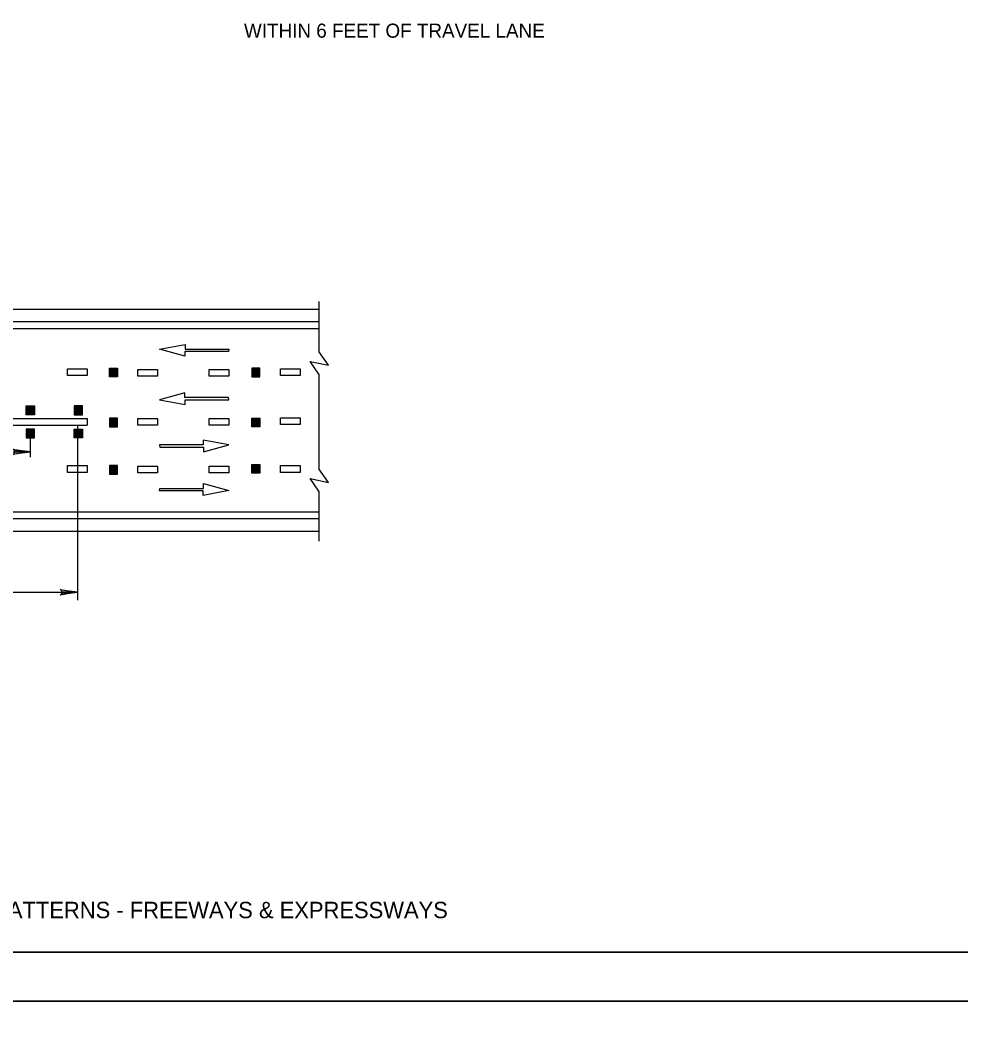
# Model space of a CAD drawing. Extents: x 639362 to 641108, y 298458 to 299646.
# Drawn here: x 639652.3 to 639939.1, y 299044.4 to 299350.7 of the extents above; entities that cross this region are included whole.
import ezdxf

# ---------------------------------------------------------------- set-up
doc = ezdxf.new("R2010")
doc.units = 0
for name, color, linetype in [('1', 7, 'Continuous'), ('2', 7, 'Continuous'), ('PLT-BNDY', 7, 'Continuous')]:
    doc.layers.add(name, color=color, linetype=linetype)

msp = doc.modelspace()

# ---------------------------------------------------------------- linework, layer by layer
at = {"layer": '1'}
for p, q in [((640188.31, 299066.63), (639402.31, 299066.63)), ((639402.31, 299066.63), (639988.31, 299066.63))]:
    msp.add_line(p, q, dxfattribs=at)
at = {"layer": '2'}
for p, q in [((639743.31, 299264.95), (639743.31, 299249.67)), ((639583.1, 299262.59), (639743.31, 299262.59)), ((639583.09, 299258.81), (639743.31, 299258.81)), ((639583.09, 299256.74), (639743.31, 299256.74)), ((639694.78, 299250.39), (639702.59, 299251.86)), ((639702.59, 299251.86), (639702.59, 299250.42)), ((639702.51, 299248.27), (639694.78, 299250.39)), ((639715.83, 299249.72), (639702.51, 299249.72)), ((639702.51, 299249.72), (639702.51, 299248.27)), ((639702.59, 299250.42), (639715.91, 299250.42)), ((639715.91, 299250.39), (639715.83, 299249.72)), ((639715.91, 299250.42), (639715.91, 299250.39)), ((639746.26, 299245.54), (639743.31, 299249.67)), ((639743.31, 299242.8), (639740.73, 299246.67)), ((639740.73, 299246.67), (639746.26, 299245.54)), ((639666.72, 299242.34), (639666.72, 299244.4)), ((639666.72, 299244.4), (639672.74, 299244.4)), ((639672.74, 299244.4), (639672.74, 299242.34)), ((639679.48, 299244.59), (639681.97, 299244.59)), ((639679.48, 299241.93), (639679.48, 299244.59)), ((639679.66, 299244.45), (639681.79, 299244.45)), ((639679.66, 299242.06), (639679.66, 299244.45)), ((639679.84, 299244.28), (639681.62, 299244.28)), ((639679.84, 299242.24), (639679.84, 299244.28)), ((639680.02, 299244.1), (639681.44, 299244.1)), ((639680.02, 299242.41), (639680.02, 299244.1)), ((639680.19, 299243.92), (639681.26, 299243.92)), ((639680.19, 299242.59), (639680.19, 299243.92)), ((639681.26, 299242.59), (639680.19, 299242.59)), ((639680.37, 299242.77), (639680.37, 299243.74)), ((639680.37, 299243.74), (639681.08, 299243.74)), ((639681.08, 299242.77), (639680.37, 299242.77)), ((639680.55, 299243.57), (639680.91, 299243.57)), ((639680.55, 299242.95), (639680.55, 299243.57)), ((639680.91, 299242.95), (639680.55, 299242.95)), ((639680.73, 299243.39), (639680.73, 299243.12)), ((639680.91, 299243.57), (639680.91, 299242.95)), ((639681.08, 299243.74), (639681.08, 299242.77)), ((639681.26, 299243.92), (639681.26, 299242.59)), ((639681.44, 299244.1), (639681.44, 299242.41)), ((639681.62, 299244.28), (639681.62, 299242.24)), ((639681.79, 299244.45), (639681.79, 299242.06)), ((639681.97, 299244.59), (639681.97, 299241.93)), ((639688.17, 299242.15), (639688.17, 299244.22)), ((639688.17, 299244.22), (639694.19, 299244.22)), ((639694.19, 299244.22), (639694.19, 299242.15)), ((639709.87, 299242.15), (639709.87, 299244.22)), ((639709.87, 299244.22), (639715.89, 299244.22)), ((639715.89, 299244.22), (639715.89, 299242.15)), ((639725.39, 299244.59), (639722.89, 299244.59)), ((639722.89, 299244.59), (639722.89, 299241.93)), ((639725.2, 299244.45), (639723.07, 299244.45)), ((639723.07, 299244.45), (639723.07, 299242.06)), ((639725.02, 299244.28), (639723.25, 299244.28)), ((639723.25, 299244.28), (639723.25, 299242.24)), ((639724.84, 299244.1), (639723.43, 299244.1)), ((639723.43, 299244.1), (639723.43, 299242.41)), ((639724.67, 299243.92), (639723.6, 299243.92)), ((639723.6, 299243.92), (639723.6, 299242.59)), ((639723.6, 299242.59), (639724.67, 299242.59)), ((639723.78, 299243.74), (639723.78, 299242.77)), ((639724.49, 299243.74), (639723.78, 299243.74)), ((639723.78, 299242.77), (639724.49, 299242.77)), ((639724.31, 299243.57), (639723.96, 299243.57)), ((639723.96, 299243.57), (639723.96, 299242.95)), ((639723.96, 299242.95), (639724.31, 299242.95)), ((639724.14, 299243.39), (639724.14, 299243.12)), ((639724.31, 299242.95), (639724.31, 299243.57)), ((639724.49, 299242.77), (639724.49, 299243.74)), ((639724.67, 299242.59), (639724.67, 299243.92)), ((639724.84, 299242.41), (639724.84, 299244.1)), ((639725.02, 299242.24), (639725.02, 299244.28)), ((639725.2, 299242.06), (639725.2, 299244.45)), ((639725.39, 299241.93), (639725.39, 299244.59)), ((639731.64, 299242.34), (639731.64, 299244.4)), ((639731.64, 299244.4), (639737.65, 299244.4)), ((639737.65, 299244.4), (639737.65, 299242.34)), ((639743.31, 299242.8), (639743.31, 299213.94)), ((639672.74, 299242.34), (639666.72, 299242.34)), ((639681.97, 299241.93), (639679.48, 299241.93)), ((639681.79, 299242.06), (639679.66, 299242.06)), ((639681.62, 299242.24), (639679.84, 299242.24)), ((639681.44, 299242.41), (639680.02, 299242.41)), ((639694.19, 299242.15), (639688.17, 299242.15)), ((639715.89, 299242.15), (639709.87, 299242.15)), ((639722.89, 299241.93), (639725.39, 299241.93)), ((639723.07, 299242.06), (639725.2, 299242.06)), ((639723.25, 299242.24), (639725.02, 299242.24)), ((639723.43, 299242.41), (639724.84, 299242.41)), ((639737.65, 299242.34), (639731.64, 299242.34)), ((639702.51, 299237.11), (639694.78, 299234.99)), ((639702.51, 299235.66), (639702.51, 299237.11)), ((639694.78, 299234.99), (639702.59, 299233.51)), ((639715.83, 299235.66), (639702.51, 299235.66)), ((639702.59, 299233.51), (639702.59, 299234.96)), ((639702.59, 299234.96), (639715.91, 299234.96)), ((639715.91, 299234.99), (639715.83, 299235.66)), ((639715.91, 299234.96), (639715.91, 299234.99)), ((639654.13, 299230.43), (639654.13, 299233.09)), ((639654.13, 299233.09), (639656.63, 299233.09)), ((639656.63, 299230.43), (639654.13, 299230.43)), ((639654.31, 299230.57), (639654.31, 299232.96)), ((639654.31, 299232.96), (639656.44, 299232.96)), ((639656.44, 299230.57), (639654.31, 299230.57)), ((639654.49, 299230.74), (639654.49, 299232.78)), ((639654.49, 299232.78), (639656.26, 299232.78)), ((639656.26, 299230.74), (639654.49, 299230.74)), ((639654.67, 299230.92), (639654.67, 299232.61)), ((639654.67, 299232.61), (639656.09, 299232.61)), ((639656.09, 299230.92), (639654.67, 299230.92)), ((639654.85, 299231.1), (639654.85, 299232.43)), ((639654.85, 299232.43), (639655.91, 299232.43)), ((639655.91, 299231.1), (639654.85, 299231.1)), ((639655.02, 299231.28), (639655.02, 299232.25)), ((639655.02, 299232.25), (639655.73, 299232.25)), ((639655.73, 299231.28), (639655.02, 299231.28)), ((639655.2, 299231.45), (639655.2, 299232.07)), ((639655.2, 299232.07), (639655.55, 299232.07)), ((639655.55, 299231.45), (639655.2, 299231.45)), ((639655.38, 299231.63), (639655.38, 299231.9)), ((639655.55, 299232.07), (639655.55, 299231.45)), ((639655.73, 299232.25), (639655.73, 299231.28)), ((639655.91, 299232.43), (639655.91, 299231.1)), ((639656.09, 299232.61), (639656.09, 299230.92)), ((639656.26, 299232.78), (639656.26, 299230.74)), ((639656.44, 299232.96), (639656.44, 299230.57)), ((639656.63, 299233.09), (639656.63, 299230.43)), ((639671.26, 299233.09), (639668.77, 299233.09)), ((639668.77, 299233.09), (639668.77, 299230.43)), ((639668.77, 299230.43), (639671.26, 299230.43)), ((639671.08, 299232.96), (639668.95, 299232.96)), ((639668.95, 299232.96), (639668.95, 299230.57)), ((639668.95, 299230.57), (639671.08, 299230.57)), ((639670.9, 299232.78), (639669.13, 299232.78)), ((639669.13, 299232.78), (639669.13, 299230.74)), ((639669.13, 299230.74), (639670.9, 299230.74)), ((639670.73, 299232.61), (639669.31, 299232.61)), ((639669.31, 299232.61), (639669.31, 299230.92)), ((639669.31, 299230.92), (639670.73, 299230.92)), ((639670.55, 299232.43), (639669.48, 299232.43)), ((639669.48, 299232.43), (639669.48, 299231.1)), ((639669.48, 299231.1), (639670.55, 299231.1)), ((639670.37, 299232.25), (639669.66, 299232.25)), ((639669.66, 299232.25), (639669.66, 299231.28)), ((639669.66, 299231.28), (639670.37, 299231.28)), ((639670.2, 299232.07), (639669.84, 299232.07)), ((639669.84, 299232.07), (639669.84, 299231.45)), ((639669.84, 299231.45), (639670.2, 299231.45)), ((639670.02, 299231.63), (639670.02, 299231.9)), ((639670.2, 299231.45), (639670.2, 299232.07)), ((639670.37, 299231.28), (639670.37, 299232.25)), ((639670.55, 299231.1), (639670.55, 299232.43)), ((639670.73, 299230.92), (639670.73, 299232.61)), ((639670.9, 299230.74), (639670.9, 299232.78)), ((639671.08, 299230.57), (639671.08, 299232.96)), ((639671.26, 299230.43), (639671.26, 299233.09)), ((639583.05, 299229.28), (639672.74, 299229.28)), ((639672.74, 299229.28), (639672.74, 299227.21)), ((639681.97, 299229.39), (639679.48, 299229.39)), ((639679.48, 299229.39), (639679.48, 299226.73)), ((639681.79, 299229.26), (639679.66, 299229.26)), ((639679.66, 299229.26), (639679.66, 299226.86)), ((639681.62, 299229.08), (639679.84, 299229.08)), ((639679.84, 299229.08), (639679.84, 299227.04)), ((639681.44, 299228.9), (639680.02, 299228.9)), ((639680.02, 299228.9), (639680.02, 299227.22)), ((639681.26, 299228.73), (639680.19, 299228.73)), ((639680.19, 299228.73), (639680.19, 299227.39)), ((639680.19, 299227.39), (639681.26, 299227.39)), ((639681.08, 299228.55), (639680.37, 299228.55)), ((639680.37, 299228.55), (639680.37, 299227.57)), ((639680.37, 299227.57), (639681.08, 299227.57)), ((639680.91, 299228.37), (639680.55, 299228.37)), ((639680.55, 299228.37), (639680.55, 299227.75)), ((639680.55, 299227.75), (639680.91, 299227.75)), ((639680.73, 299227.93), (639680.73, 299228.19)), ((639680.91, 299227.75), (639680.91, 299228.37)), ((639681.08, 299227.57), (639681.08, 299228.55)), ((639681.26, 299227.39), (639681.26, 299228.73)), ((639681.44, 299227.22), (639681.44, 299228.9)), ((639681.62, 299227.04), (639681.62, 299229.08)), ((639681.79, 299226.86), (639681.79, 299229.26)), ((639681.97, 299226.73), (639681.97, 299229.39)), ((639688.17, 299227.21), (639688.17, 299229.28)), ((639688.17, 299229.28), (639694.19, 299229.28)), ((639694.19, 299229.28), (639694.19, 299227.21)), ((639709.87, 299227.21), (639709.87, 299229.28)), ((639709.87, 299229.28), (639715.89, 299229.28)), ((639715.89, 299229.28), (639715.89, 299227.21)), ((639722.89, 299226.73), (639722.89, 299229.39)), ((639722.89, 299229.39), (639725.39, 299229.39)), ((639723.07, 299226.86), (639723.07, 299229.26)), ((639723.07, 299229.26), (639725.2, 299229.26)), ((639723.25, 299227.04), (639723.25, 299229.08)), ((639723.25, 299229.08), (639725.02, 299229.08)), ((639723.43, 299227.22), (639723.43, 299228.9)), ((639723.43, 299228.9), (639724.84, 299228.9)), ((639723.6, 299227.39), (639723.6, 299228.73)), ((639723.6, 299228.73), (639724.67, 299228.73)), ((639724.67, 299227.39), (639723.6, 299227.39)), ((639723.78, 299227.57), (639723.78, 299228.55)), ((639723.78, 299228.55), (639724.49, 299228.55)), ((639724.49, 299227.57), (639723.78, 299227.57)), ((639723.96, 299227.75), (639723.96, 299228.37)), ((639723.96, 299228.37), (639724.31, 299228.37)), ((639724.31, 299227.75), (639723.96, 299227.75)), ((639724.14, 299227.93), (639724.14, 299228.19)), ((639724.31, 299228.37), (639724.31, 299227.75)), ((639724.49, 299228.55), (639724.49, 299227.57)), ((639724.67, 299228.73), (639724.67, 299227.39)), ((639724.84, 299228.9), (639724.84, 299227.22)), ((639725.02, 299229.08), (639725.02, 299227.04)), ((639725.2, 299229.26), (639725.2, 299226.86)), ((639725.39, 299229.39), (639725.39, 299226.73)), ((639731.64, 299227.4), (639731.64, 299229.46)), ((639731.64, 299229.46), (639737.65, 299229.46)), ((639737.65, 299227.4), (639731.64, 299227.4)), ((639737.65, 299229.46), (639737.65, 299227.4)), ((639583.05, 299227.21), (639672.74, 299227.21)), ((639656.63, 299226.05), (639654.13, 299226.05)), ((639654.13, 299226.05), (639654.13, 299223.4)), ((639656.44, 299225.92), (639654.31, 299225.92)), ((639654.31, 299225.92), (639654.31, 299223.53)), ((639656.26, 299225.75), (639654.49, 299225.75)), ((639654.49, 299225.75), (639654.49, 299223.71)), ((639656.09, 299225.57), (639654.67, 299225.57)), ((639654.67, 299225.57), (639654.67, 299223.88)), ((639655.91, 299225.39), (639654.85, 299225.39)), ((639654.85, 299225.39), (639654.85, 299224.06)), ((639655.02, 299225.21), (639655.02, 299224.24)), ((639655.73, 299225.21), (639655.02, 299225.21)), ((639655.02, 299224.24), (639655.73, 299224.24)), ((639655.55, 299225.03), (639655.2, 299225.03)), ((639655.2, 299225.03), (639655.2, 299224.41)), ((639655.2, 299224.41), (639655.55, 299224.41)), ((639655.38, 299224.86), (639655.38, 299224.59)), ((639655.55, 299224.41), (639655.55, 299225.03)), ((639655.73, 299224.24), (639655.73, 299225.21)), ((639655.91, 299224.06), (639655.91, 299225.39)), ((639656.09, 299223.88), (639656.09, 299225.57)), ((639656.26, 299223.71), (639656.26, 299225.75)), ((639656.44, 299223.53), (639656.44, 299225.92)), ((639656.63, 299223.4), (639656.63, 299226.05)), ((639668.77, 299226.05), (639671.26, 299226.05)), ((639668.77, 299223.4), (639668.77, 299226.05)), ((639668.95, 299225.92), (639671.08, 299225.92)), ((639668.95, 299223.53), (639668.95, 299225.92)), ((639669.13, 299225.75), (639670.9, 299225.75)), ((639669.13, 299223.71), (639669.13, 299225.75)), ((639669.31, 299225.57), (639670.73, 299225.57)), ((639669.31, 299223.88), (639669.31, 299225.57)), ((639669.48, 299225.39), (639670.55, 299225.39)), ((639669.48, 299224.06), (639669.48, 299225.39)), ((639669.66, 299224.24), (639669.66, 299225.21)), ((639669.66, 299225.21), (639670.37, 299225.21)), ((639670.37, 299224.24), (639669.66, 299224.24)), ((639669.77, 299227.21), (639669.77, 299173.91)), ((639669.84, 299225.03), (639670.2, 299225.03)), ((639669.84, 299224.41), (639669.84, 299225.03)), ((639670.2, 299224.41), (639669.84, 299224.41)), ((639670.02, 299224.86), (639670.02, 299224.59)), ((639670.2, 299225.03), (639670.2, 299224.41)), ((639670.37, 299225.21), (639670.37, 299224.24)), ((639670.55, 299225.39), (639670.55, 299224.06)), ((639670.73, 299225.57), (639670.73, 299223.88)), ((639670.9, 299225.75), (639670.9, 299223.71)), ((639671.08, 299225.92), (639671.08, 299223.53)), ((639671.26, 299226.05), (639671.26, 299223.4)), ((639679.48, 299226.73), (639681.97, 299226.73)), ((639679.66, 299226.86), (639681.79, 299226.86)), ((639679.84, 299227.04), (639681.62, 299227.04)), ((639680.02, 299227.22), (639681.44, 299227.22)), ((639694.19, 299227.21), (639688.17, 299227.21)), ((639715.89, 299227.21), (639709.87, 299227.21)), ((639725.39, 299226.73), (639722.89, 299226.73)), ((639725.2, 299226.86), (639723.07, 299226.86)), ((639725.02, 299227.04), (639723.25, 299227.04)), ((639724.84, 299227.22), (639723.43, 299227.22)), ((639654.13, 299223.4), (639656.63, 299223.4)), ((639654.31, 299223.53), (639656.44, 299223.53)), ((639654.49, 299223.71), (639656.26, 299223.71)), ((639654.67, 299223.88), (639656.09, 299223.88)), ((639654.85, 299224.06), (639655.91, 299224.06)), ((639655.34, 299224.09), (639655.34, 299217.48)), ((639671.26, 299223.4), (639668.77, 299223.4)), ((639671.08, 299223.53), (639668.95, 299223.53)), ((639670.9, 299223.71), (639669.13, 299223.71)), ((639670.73, 299223.88), (639669.31, 299223.88)), ((639670.55, 299224.06), (639669.48, 299224.06)), ((639694.76, 299221.26), (639694.76, 299221.23)), ((639708.08, 299221.26), (639694.76, 299221.26)), ((639694.76, 299221.23), (639694.84, 299220.56)), ((639715.89, 299221.23), (639708.08, 299222.71)), ((639708.08, 299222.71), (639708.08, 299221.26)), ((639708.16, 299219.12), (639715.89, 299221.23)), ((639640.26, 299219.12), (639655.34, 299219.12)), ((639694.84, 299220.56), (639708.16, 299220.56)), ((639708.16, 299220.56), (639708.16, 299219.12)), ((639722.89, 299212.56), (639722.89, 299215.22)), ((639722.89, 299215.22), (639725.39, 299215.22)), ((639723.07, 299212.69), (639723.07, 299215.09)), ((639723.07, 299215.09), (639725.2, 299215.09)), ((639725.2, 299215.09), (639725.2, 299212.69)), ((639725.39, 299215.22), (639725.39, 299212.56)), ((639666.72, 299212.85), (639666.72, 299214.91)), ((639666.72, 299214.91), (639672.74, 299214.91)), ((639672.74, 299212.85), (639666.72, 299212.85)), ((639672.74, 299214.91), (639672.74, 299212.85)), ((639681.97, 299214.95), (639679.48, 299214.95)), ((639679.48, 299214.95), (639679.48, 299212.3)), ((639679.48, 299212.3), (639681.97, 299212.3)), ((639681.79, 299214.82), (639679.66, 299214.82)), ((639679.66, 299214.82), (639679.66, 299212.43)), ((639679.66, 299212.43), (639681.79, 299212.43)), ((639681.62, 299214.64), (639679.84, 299214.64)), ((639679.84, 299214.64), (639679.84, 299212.61)), ((639679.84, 299212.61), (639681.62, 299212.61)), ((639681.44, 299214.47), (639680.02, 299214.47)), ((639680.02, 299214.47), (639680.02, 299212.78)), ((639680.02, 299212.78), (639681.44, 299212.78)), ((639681.26, 299214.29), (639680.19, 299214.29)), ((639680.19, 299214.29), (639680.19, 299212.96)), ((639680.19, 299212.96), (639681.26, 299212.96)), ((639681.08, 299214.12), (639680.37, 299214.12)), ((639680.37, 299214.12), (639680.37, 299213.14)), ((639680.37, 299213.14), (639681.08, 299213.14)), ((639680.91, 299213.94), (639680.55, 299213.94)), ((639680.55, 299213.94), (639680.55, 299213.32)), ((639680.55, 299213.32), (639680.91, 299213.32)), ((639680.73, 299213.49), (639680.73, 299213.76)), ((639680.91, 299213.32), (639680.91, 299213.94)), ((639681.08, 299213.14), (639681.08, 299214.12)), ((639681.26, 299212.96), (639681.26, 299214.29)), ((639681.44, 299212.78), (639681.44, 299214.47)), ((639681.62, 299212.61), (639681.62, 299214.64)), ((639681.79, 299212.43), (639681.79, 299214.82)), ((639681.97, 299212.3), (639681.97, 299214.95)), ((639688.17, 299212.66), (639688.17, 299214.72)), ((639688.17, 299214.72), (639694.19, 299214.72)), ((639694.19, 299212.66), (639688.17, 299212.66)), ((639694.19, 299214.72), (639694.19, 299212.66)), ((639709.87, 299212.66), (639709.87, 299214.72)), ((639709.87, 299214.72), (639715.89, 299214.72)), ((639715.89, 299212.66), (639709.87, 299212.66)), ((639715.89, 299214.72), (639715.89, 299212.66)), ((639725.39, 299212.56), (639722.89, 299212.56)), ((639725.2, 299212.69), (639723.07, 299212.69)), ((639723.25, 299212.87), (639723.25, 299214.91)), ((639723.25, 299214.91), (639725.02, 299214.91)), ((639725.02, 299212.87), (639723.25, 299212.87)), ((639723.43, 299213.05), (639723.43, 299214.74)), ((639723.43, 299214.74), (639724.84, 299214.74)), ((639724.84, 299213.05), (639723.43, 299213.05)), ((639723.6, 299213.23), (639723.6, 299214.56)), ((639723.6, 299214.56), (639724.67, 299214.56)), ((639724.67, 299213.23), (639723.6, 299213.23)), ((639723.78, 299213.4), (639723.78, 299214.38)), ((639723.78, 299214.38), (639724.49, 299214.38)), ((639724.49, 299213.4), (639723.78, 299213.4)), ((639723.96, 299213.58), (639723.96, 299214.2)), ((639723.96, 299214.2), (639724.31, 299214.2)), ((639724.31, 299213.58), (639723.96, 299213.58)), ((639724.14, 299213.76), (639724.14, 299214.02)), ((639724.31, 299214.2), (639724.31, 299213.58)), ((639724.49, 299214.38), (639724.49, 299213.4)), ((639724.67, 299214.56), (639724.67, 299213.23)), ((639724.84, 299214.74), (639724.84, 299213.05)), ((639725.02, 299214.91), (639725.02, 299212.87)), ((639731.64, 299212.85), (639731.64, 299214.91)), ((639731.64, 299214.91), (639737.65, 299214.91)), ((639737.65, 299212.85), (639731.64, 299212.85)), ((639737.65, 299214.91), (639737.65, 299212.85)), ((639746.26, 299209.8), (639743.31, 299213.94)), ((639708.16, 299207.96), (639708.16, 299209.41)), ((639708.16, 299209.41), (639715.89, 299207.29)), ((639743.31, 299207.07), (639740.73, 299210.94)), ((639740.73, 299210.94), (639746.26, 299209.8)), ((639694.76, 299207.29), (639694.84, 299207.96)), ((639694.76, 299207.26), (639694.76, 299207.29)), ((639708.08, 299207.26), (639694.76, 299207.26)), ((639694.84, 299207.96), (639708.16, 299207.96)), ((639715.89, 299207.29), (639708.08, 299205.81)), ((639708.08, 299205.81), (639708.08, 299207.26)), ((639743.31, 299207.07), (639743.31, 299191.88)), ((639583.1, 299200.77), (639743.31, 299200.77)), ((639743.31, 299200.77), (639743.31, 299198.71)), ((639743.31, 299198.71), (639583.09, 299198.71)), ((639583.1, 299194.92), (639743.31, 299194.92)), ((639583.1, 299176.29), (639669.77, 299176.29))]:
    msp.add_line(p, q, dxfattribs=at)
for points in [[(639650.34, 299219.74), (639650.53, 299219.38), (639655.34, 299219.12), (639650.34, 299219.74), (639650.09, 299219.96), (639655.34, 299219.12), (639650.53, 299218.88), (639650.36, 299218.52), (639655.34, 299219.12), (639650.09, 299218.28), (639650.36, 299218.52)], [(639664.78, 299176.92), (639664.96, 299176.55), (639669.77, 299176.29), (639664.78, 299176.92), (639664.52, 299177.14), (639669.77, 299176.29), (639664.97, 299176.05), (639664.79, 299175.69), (639669.77, 299176.29), (639664.52, 299175.45), (639664.79, 299175.69)]]:
    msp.add_lwpolyline(points, dxfattribs=at)
at = {"layer": 'PLT-BNDY'}
for points in [[(639362.31, 299645.63), (640203.31, 299645.63), (640203.31, 299051.63), (639362.31, 299051.63)], [(639362.31, 299051.63), (640203.31, 299051.63), (640203.31, 298457.63), (639362.31, 298457.63)]]:
    msp.add_lwpolyline(points, close=True, dxfattribs=at)

# ---------------------------------------------------------------- texts
at = {"layer": '2'}
for s, height, p in [('WITHIN 6 FEET OF TRAVEL LANE', 4.3, (639720.51, 299345.35)), ('INSTALLATION PATTERNS - FREEWAYS & EXPRESSWAYS', 5, (639594.67, 299076.94))]:
    msp.add_text(s, height=height, dxfattribs=at).set_placement(p)

doc.saveas('drawing.dxf')
